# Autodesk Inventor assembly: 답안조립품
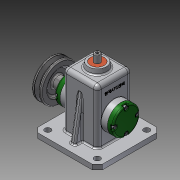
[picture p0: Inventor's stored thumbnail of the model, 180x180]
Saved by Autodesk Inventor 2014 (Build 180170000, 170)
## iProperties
Created: 2016-02
Part Number: 답안조립품
Document SubType Name: Assembly
Designer: S. S. MOON
Author: S. S. MOON
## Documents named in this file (16)
- C:\Users\Administrator\Desktop\460211V1035\답안조립품.iam
- C:\Users\Administrator\Desktop\460211V1035\1-본체.ipt
- C:\Users\Administrator\Desktop\460211V1035\V벨트풀리.ipt
- C:\Users\Administrator\Desktop\460211V1035\고정핀 1.2 x 10.ipt
- C:\Users\Administrator\Desktop\460211V1035\뒤커버.ipt
- C:\Users\Administrator\Desktop\460211V1035\링크.ipt
- C:\Users\Administrator\Desktop\460211V1035\멈춤나사 M3x8.ipt
- C:\Users\Administrator\Desktop\460211V1035\베어링 12 x 32 x 10.ipt
- C:\Users\Administrator\Desktop\460211V1035\볼트 M4 x 12.ipt
- C:\Users\Administrator\Desktop\460211V1035\부시.ipt
- C:\Users\Administrator\Desktop\460211V1035\슬라이드.ipt
- C:\Users\Administrator\Desktop\460211V1035\앞커버.ipt
- C:\Users\Administrator\Desktop\460211V1035\오일실 12 25 7.ipt
- C:\Users\Administrator\Desktop\460211V1035\키 4 x 4 x 10.ipt
- C:\Users\Administrator\Desktop\460211V1035\편심축.ipt
- C:\Users\Administrator\Desktop\460211V1035\핀 5 x 18.ipt
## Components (12 placed, 5 different names)
1. 1-본체:1
2. V벨트풀리:1
3. 고정핀 1.2 x 10:1
4. ISO 4762 M4 x 12:1 — 각도:2, 각도:3, 각도:4, 각도:5
5. 핀 5 x 18:1 — 각도:1
6. ISO 4762 M4 x 12:2 — 각도:5
7. ISO 4762 M4 x 12:3 — 각도:3
8. ISO 4762 M4 x 12:4 — 각도:4
9. ISO 4762 M4 x 12:5 — 각도:9
10. ISO 4762 M4 x 12:6 — 각도:6, 각도:7
11. ISO 4762 M4 x 12:7 — 각도:7, 각도:8
12. ISO 4762 M4 x 12:8 — 각도:8, 각도:9
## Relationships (9: Angle 9)
- 각도:1 [Angle]: 핀 5 x 18:1
- 각도:2 [Angle]: ISO 4762 M4 x 12:1
- 각도:3 [Angle]: ISO 4762 M4 x 12:1 ↔ ISO 4762 M4 x 12:3
- 각도:4 [Angle]: ISO 4762 M4 x 12:1 ↔ ISO 4762 M4 x 12:4
- 각도:5 [Angle]: ISO 4762 M4 x 12:1 ↔ ISO 4762 M4 x 12:2
- 각도:6 [Angle]: ISO 4762 M4 x 12:6
- 각도:7 [Angle]: ISO 4762 M4 x 12:6 ↔ ISO 4762 M4 x 12:7
- 각도:8 [Angle]: ISO 4762 M4 x 12:7 ↔ ISO 4762 M4 x 12:8
- 각도:9 [Angle]: ISO 4762 M4 x 12:5 ↔ ISO 4762 M4 x 12:8
